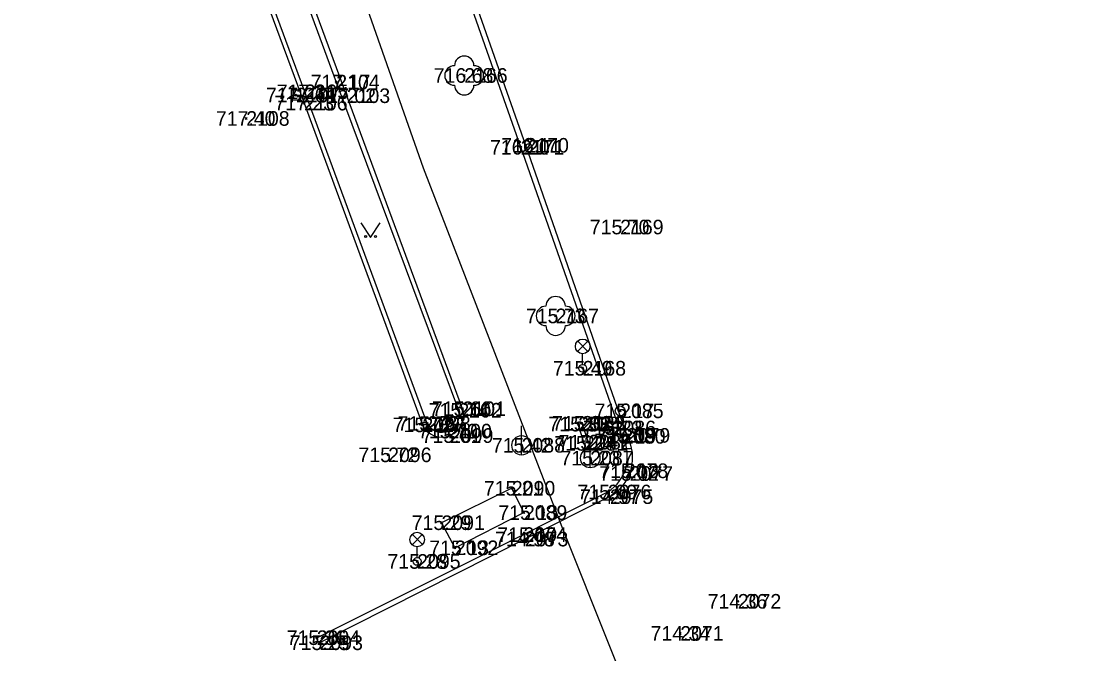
# Model space of a CAD drawing. Extents: x -844765 to -843273, y -997542 to -995529.
# Drawn here: x -844610.3 to -844555.2, y -995987.5 to -995955 of the extents above; entities that cross this region are included whole.
import ezdxf

# ---------------------------------------------------------------- set-up
doc = ezdxf.new("R2010")
doc.units = 0
for name, color, linetype in [('Betonový strop', 7, 'Continuous'), ('Bod', 7, 'Continuous'), ('Dno', 7, 'Continuous'), ('Doplněk polohopisu', 7, 'Continuous'), ('Groma', 7, 'Continuous'), ('Klenba', 7, 'Continuous'), ('Osa', 7, 'Continuous'), ('Sítě podzemní nerozlišené', 7, 'Continuous'), ('Výškopis', 7, 'Continuous'), ('Číslo bodu', 7, 'Continuous'), ('Řezy', 7, 'Continuous')]:
    doc.layers.add(name, color=color, linetype=linetype)

msp = doc.modelspace()

# ---------------------------------------------------------------- linework, layer by layer
at = {"layer": 'Betonový strop'}
for points in [[(-844629.12, -995861.21), (-844625.65, -995859.15), (-844621.49, -995856.6), (-844620.48, -995855.21), (-844619.24, -995854.94), (-844616.52, -995865.52), (-844610.55, -995885.46), (-844605.08, -995902.6), (-844600.8, -995914.77), (-844593.72, -995934.94), (-844584.42, -995961.39), (-844579.21, -995976.3)], [(-844579.45, -995976.35), (-844584.66, -995961.49), (-844593.98, -995934.98), (-844601.34, -995914.07), (-844605.29, -995902.68), (-844610.78, -995885.51), (-844616.77, -995865.64), (-844619.45, -995855.22), (-844620.38, -995855.56), (-844621.35, -995856.86), (-844628.99, -995861.43)], [(-844606.82, -995923.77), (-844594.15, -995958.14), (-844587.87, -995975.01)], [(-844587.66, -995974.93), (-844593.61, -995958.84), (-844606.58, -995923.7)], [(-844608.68, -995924.48), (-844595.8, -995959.22), (-844589.72, -995975.76)], [(-844589.47, -995975.69), (-844595.77, -995958.64), (-844608.43, -995924.4)], [(-844595.15, -995986.7), (-844584.52, -995981.4), (-844580.18, -995979.21)], [(-844580.08, -995979.45), (-844584.45, -995981.63), (-844595.01, -995986.96)]]:
    msp.add_lwpolyline(points, dxfattribs=at)
for centre, radius, start, end in [((-844588.717, -995975.278), 1.113, 205.6529, 18.2373), ((-844588.705, -995975.269), 0.874, 208.8225, 17.2285), ((-844581.342, -995977.39), 2.159, 302.5632, 28.7994), ((-844581.221, -995977.44), 2.312, 299.5827, 29.538)]:
    msp.add_arc(centre, radius, start, end, dxfattribs=at)
at = {"layer": 'Bod'}
msp.add_circle((-844579.55, -995975.04), 0.25, dxfattribs=at)
at = {"layer": 'Dno'}
msp.add_lwpolyline([(-844592.888, -995965.38), (-844592.388, -995966.13), (-844591.888, -995965.38)], dxfattribs=at)
for centre in [(-844592.638, -995966.08), (-844592.138, -995966.08)]:
    msp.add_circle(centre, 0.05, dxfattribs=at)
at = {"layer": 'Doplněk polohopisu'}
for p, q in [((-844596.47, -995958.81), (-844595.97, -995958.81)), ((-844584.62, -995977.31), (-844584.62, -995975.81)), ((-844580.19, -995975.92), (-844579.69, -995975.92)), ((-844581.09, -995977.97), (-844581.09, -995976.47))]:
    msp.add_line(p, q, dxfattribs=at)
for points in [[(-844596.47, -995959.06), (-844595.97, -995959.06), (-844595.97, -995958.56), (-844596.47, -995958.56)], [(-844580.19, -995976.17), (-844579.69, -995976.17), (-844579.69, -995975.67), (-844580.19, -995975.67)]]:
    msp.add_lwpolyline(points, close=True, dxfattribs=at)
for centre in [(-844584.62, -995976.81), (-844581.09, -995977.47)]:
    msp.add_circle(centre, 0.5, dxfattribs=at)
at = {"layer": 'Groma'}
for p, q in [((-844581.744, -995971.988), (-844581.216, -995971.46)), ((-844581.208, -995971.985), (-844581.736, -995971.456)), ((-844581.48, -995972.65), (-844581.48, -995972.1)), ((-844590.254, -995981.918), (-844589.726, -995981.39)), ((-844589.718, -995981.915), (-844590.246, -995981.386)), ((-844589.99, -995982.58), (-844589.99, -995982.03))]:
    msp.add_line(p, q, dxfattribs=at)
for centre, radius in [((-844581.48, -995971.725), 0.375), ((-844581.48, -995972.85), 0.2), ((-844589.99, -995981.655), 0.375), ((-844589.99, -995982.78), 0.2)]:
    msp.add_circle(centre, radius, dxfattribs=at)
at = {"layer": 'Klenba'}
for p, q in [((-844581.71, -995975.72), (-844581.52, -995975.68)), ((-844581.41, -995976.71), (-844581.71, -995975.72)), ((-844581.52, -995975.68), (-844581.19, -995976.65)), ((-844581.19, -995976.65), (-844581.41, -995976.71)), ((-844585.12, -995979.02), (-844588.74, -995980.79)), ((-844584.5, -995980.27), (-844585.12, -995979.02)), ((-844588.05, -995982.08), (-844584.5, -995980.27)), ((-844588.74, -995980.79), (-844588.05, -995982.08))]:
    msp.add_line(p, q, dxfattribs=at)
at = {"layer": 'Osa'}
msp.add_lwpolyline([(-844555.208, -996045.307), (-844559.6, -996036.37), (-844563.495, -996027.16), (-844571.238, -996008.81), (-844575.085, -995999.67), (-844582.535, -995981.015), (-844589.66, -995962.57), (-844596.305, -995943.685), (-844602.165, -995924.63), (-844608.085, -995905.52), (-844613.78, -995886.51), (-844619.57, -995867.42), (-844624.395, -995848.01), (-844628.94, -995828.61), (-844632.81, -995809.025), (-844636.18, -995789.375)], dxfattribs=at)
at = {"layer": 'Sítě podzemní nerozlišené'}
for p, q in [((-844587.57, -995957.8), (-844587.62, -995957.75)), ((-844587.57, -995957.8), (-844587.62, -995957.85)), ((-844587.57, -995957.8), (-844587.52, -995957.75)), ((-844587.57, -995957.8), (-844587.52, -995957.85)), ((-844594.15, -995958.14), (-844594.2, -995958.09)), ((-844594.15, -995958.14), (-844594.2, -995958.19)), ((-844594.15, -995958.14), (-844594.1, -995958.09)), ((-844594.15, -995958.14), (-844594.1, -995958.19)), ((-844596.22, -995958.81), (-844596.27, -995958.76)), ((-844596.22, -995958.81), (-844596.27, -995958.86)), ((-844596.22, -995958.81), (-844596.17, -995958.76)), ((-844596.22, -995958.81), (-844596.17, -995958.86)), ((-844595.77, -995958.64), (-844595.82, -995958.59)), ((-844595.77, -995958.64), (-844595.82, -995958.69)), ((-844595.77, -995958.64), (-844595.72, -995958.59)), ((-844595.77, -995958.64), (-844595.72, -995958.69)), ((-844593.61, -995958.84), (-844593.66, -995958.79)), ((-844593.61, -995958.84), (-844593.66, -995958.89)), ((-844593.61, -995958.84), (-844593.56, -995958.79)), ((-844593.61, -995958.84), (-844593.56, -995958.89)), ((-844595.8, -995959.22), (-844595.85, -995959.17)), ((-844595.8, -995959.22), (-844595.85, -995959.27)), ((-844595.8, -995959.22), (-844595.75, -995959.17)), ((-844595.8, -995959.22), (-844595.75, -995959.27)), ((-844598.78, -995960.01), (-844598.83, -995959.96)), ((-844598.78, -995960.01), (-844598.83, -995960.06)), ((-844598.78, -995960.01), (-844598.73, -995959.96)), ((-844598.78, -995960.01), (-844598.73, -995960.06)), ((-844584.66, -995961.49), (-844584.71, -995961.44)), ((-844584.66, -995961.49), (-844584.71, -995961.54)), ((-844584.66, -995961.49), (-844584.61, -995961.44)), ((-844584.66, -995961.49), (-844584.61, -995961.54)), ((-844584.42, -995961.39), (-844584.47, -995961.34)), ((-844584.42, -995961.39), (-844584.47, -995961.44)), ((-844584.42, -995961.39), (-844584.37, -995961.34)), ((-844584.42, -995961.39), (-844584.37, -995961.44)), ((-844579.55, -995965.59), (-844579.6, -995965.54)), ((-844579.55, -995965.59), (-844579.6, -995965.64)), ((-844579.55, -995965.59), (-844579.5, -995965.54)), ((-844579.55, -995965.59), (-844579.5, -995965.64)), ((-844582.87, -995970.16), (-844582.92, -995970.11)), ((-844582.87, -995970.16), (-844582.82, -995970.11)), ((-844582.87, -995970.16), (-844582.92, -995970.21)), ((-844582.87, -995970.16), (-844582.82, -995970.21)), ((-844581.48, -995972.85), (-844581.53, -995972.8)), ((-844581.48, -995972.85), (-844581.53, -995972.9)), ((-844581.48, -995972.85), (-844581.43, -995972.8)), ((-844581.48, -995972.85), (-844581.43, -995972.9)), ((-844587.87, -995975.01), (-844587.92, -995974.96)), ((-844587.87, -995975.01), (-844587.92, -995975.06)), ((-844587.87, -995975.01), (-844587.82, -995974.96)), ((-844587.87, -995975.01), (-844587.82, -995975.06)), ((-844587.66, -995974.93), (-844587.71, -995974.88)), ((-844587.66, -995974.93), (-844587.71, -995974.98)), ((-844587.66, -995974.93), (-844587.61, -995974.88)), ((-844587.66, -995974.93), (-844587.61, -995974.98)), ((-844579.55, -995975.04), (-844579.6, -995974.99)), ((-844579.55, -995975.04), (-844579.6, -995975.09)), ((-844579.55, -995975.04), (-844579.5, -995974.99)), ((-844579.55, -995975.04), (-844579.5, -995975.09)), ((-844581.52, -995975.68), (-844581.57, -995975.63)), ((-844581.52, -995975.68), (-844581.47, -995975.63)), ((-844589.72, -995975.76), (-844589.77, -995975.71)), ((-844589.72, -995975.76), (-844589.77, -995975.81)), ((-844589.72, -995975.76), (-844589.67, -995975.71)), ((-844589.72, -995975.76), (-844589.67, -995975.81)), ((-844589.47, -995975.69), (-844589.52, -995975.64)), ((-844589.47, -995975.69), (-844589.52, -995975.74)), ((-844589.47, -995975.69), (-844589.42, -995975.64)), ((-844589.47, -995975.69), (-844589.42, -995975.74)), ((-844588.38, -995976.08), (-844588.43, -995976.03)), ((-844588.38, -995976.08), (-844588.43, -995976.13)), ((-844588.38, -995976.08), (-844588.33, -995976.03)), ((-844588.38, -995976.08), (-844588.33, -995976.13)), ((-844581.71, -995975.72), (-844581.76, -995975.67)), ((-844581.71, -995975.72), (-844581.76, -995975.77)), ((-844581.71, -995975.72), (-844581.66, -995975.67)), ((-844581.71, -995975.72), (-844581.66, -995975.77)), ((-844581.52, -995975.68), (-844581.57, -995975.73)), ((-844581.52, -995975.68), (-844581.47, -995975.73)), ((-844579.94, -995975.92), (-844579.99, -995975.87)), ((-844579.94, -995975.92), (-844579.99, -995975.97)), ((-844579.94, -995975.92), (-844579.89, -995975.87)), ((-844579.94, -995975.92), (-844579.89, -995975.97)), ((-844588.3, -995976.31), (-844588.35, -995976.26)), ((-844588.3, -995976.31), (-844588.35, -995976.36)), ((-844588.3, -995976.31), (-844588.25, -995976.26)), ((-844588.3, -995976.31), (-844588.25, -995976.36)), ((-844581.41, -995976.71), (-844581.46, -995976.66)), ((-844581.41, -995976.71), (-844581.46, -995976.76)), ((-844581.41, -995976.71), (-844581.36, -995976.66)), ((-844581.41, -995976.71), (-844581.36, -995976.76)), ((-844581.19, -995976.65), (-844581.24, -995976.6)), ((-844581.19, -995976.65), (-844581.24, -995976.7)), ((-844581.19, -995976.65), (-844581.14, -995976.6)), ((-844581.19, -995976.65), (-844581.14, -995976.7)), ((-844579.45, -995976.35), (-844579.5, -995976.3)), ((-844579.45, -995976.35), (-844579.5, -995976.4)), ((-844579.45, -995976.35), (-844579.4, -995976.3)), ((-844579.45, -995976.35), (-844579.4, -995976.4)), ((-844579.21, -995976.3), (-844579.26, -995976.25)), ((-844579.21, -995976.3), (-844579.26, -995976.35)), ((-844579.21, -995976.3), (-844579.16, -995976.25)), ((-844579.21, -995976.3), (-844579.16, -995976.35)), ((-844591.48, -995977.3), (-844591.53, -995977.25)), ((-844591.48, -995977.3), (-844591.43, -995977.25)), ((-844584.62, -995976.81), (-844584.67, -995976.76)), ((-844584.62, -995976.81), (-844584.67, -995976.86)), ((-844584.62, -995976.81), (-844584.57, -995976.76)), ((-844584.62, -995976.81), (-844584.57, -995976.86)), ((-844591.48, -995977.3), (-844591.53, -995977.35)), ((-844591.48, -995977.3), (-844591.43, -995977.35)), ((-844581.09, -995977.47), (-844581.14, -995977.42)), ((-844581.09, -995977.47), (-844581.14, -995977.52)), ((-844581.09, -995977.47), (-844581.04, -995977.42)), ((-844581.09, -995977.47), (-844581.04, -995977.52)), ((-844579.31, -995978.12), (-844579.36, -995978.07)), ((-844579.31, -995978.12), (-844579.36, -995978.17)), ((-844579.31, -995978.12), (-844579.26, -995978.07)), ((-844579.31, -995978.12), (-844579.26, -995978.17)), ((-844579.06, -995978.26), (-844579.11, -995978.21)), ((-844579.06, -995978.26), (-844579.11, -995978.31)), ((-844579.06, -995978.26), (-844579.01, -995978.21)), ((-844579.06, -995978.26), (-844579.01, -995978.31)), ((-844585.12, -995979.02), (-844585.17, -995978.97)), ((-844585.12, -995979.02), (-844585.17, -995979.07)), ((-844585.12, -995979.02), (-844585.07, -995978.97)), ((-844585.12, -995979.02), (-844585.07, -995979.07)), ((-844580.18, -995979.21), (-844580.23, -995979.16)), ((-844580.18, -995979.21), (-844580.23, -995979.26)), ((-844580.18, -995979.21), (-844580.13, -995979.16)), ((-844580.18, -995979.21), (-844580.13, -995979.26)), ((-844580.08, -995979.45), (-844580.13, -995979.4)), ((-844580.08, -995979.45), (-844580.13, -995979.5)), ((-844580.08, -995979.45), (-844580.03, -995979.4)), ((-844580.08, -995979.45), (-844580.03, -995979.5)), ((-844584.5, -995980.27), (-844584.55, -995980.22)), ((-844584.5, -995980.27), (-844584.55, -995980.32)), ((-844584.5, -995980.27), (-844584.45, -995980.22)), ((-844584.5, -995980.27), (-844584.45, -995980.32)), ((-844588.74, -995980.79), (-844588.79, -995980.74)), ((-844588.74, -995980.79), (-844588.79, -995980.84)), ((-844588.74, -995980.79), (-844588.69, -995980.74)), ((-844588.74, -995980.79), (-844588.69, -995980.84)), ((-844584.52, -995981.4), (-844584.57, -995981.35)), ((-844584.52, -995981.4), (-844584.57, -995981.45)), ((-844584.52, -995981.4), (-844584.47, -995981.35)), ((-844584.52, -995981.4), (-844584.47, -995981.45)), ((-844584.45, -995981.63), (-844584.5, -995981.58)), ((-844584.45, -995981.63), (-844584.5, -995981.68)), ((-844584.45, -995981.63), (-844584.4, -995981.58)), ((-844584.45, -995981.63), (-844584.4, -995981.68)), ((-844588.05, -995982.08), (-844588.1, -995982.03)), ((-844588.05, -995982.08), (-844588.1, -995982.13)), ((-844588.05, -995982.08), (-844588, -995982.03)), ((-844588.05, -995982.08), (-844588, -995982.13)), ((-844589.99, -995982.78), (-844590.04, -995982.73)), ((-844589.99, -995982.78), (-844590.04, -995982.83)), ((-844589.99, -995982.78), (-844589.94, -995982.73)), ((-844589.99, -995982.78), (-844589.94, -995982.83)), ((-844573.5, -995984.83), (-844573.55, -995984.78)), ((-844573.5, -995984.83), (-844573.55, -995984.88)), ((-844573.5, -995984.83), (-844573.45, -995984.78)), ((-844573.5, -995984.83), (-844573.45, -995984.88)), ((-844595.15, -995986.7), (-844595.2, -995986.65)), ((-844595.15, -995986.7), (-844595.1, -995986.65)), ((-844576.46, -995986.48), (-844576.51, -995986.43)), ((-844576.46, -995986.48), (-844576.51, -995986.53)), ((-844576.46, -995986.48), (-844576.41, -995986.43)), ((-844576.46, -995986.48), (-844576.41, -995986.53)), ((-844595.15, -995986.7), (-844595.2, -995986.75)), ((-844595.15, -995986.7), (-844595.1, -995986.75)), ((-844595.01, -995986.96), (-844595.06, -995986.91)), ((-844595.01, -995986.96), (-844595.06, -995987.01)), ((-844595.01, -995986.96), (-844594.96, -995986.91)), ((-844595.01, -995986.96), (-844594.96, -995987.01))]:
    msp.add_line(p, q, dxfattribs=at)
at = {"layer": 'Výškopis'}
for centre in [(-844587.57, -995957.8), (-844582.87, -995970.16)]:
    msp.add_circle(centre, 0.0005, dxfattribs=at)
for centre, start, end in [((-844587.57, -995957.3), 0, 180), ((-844588.07, -995957.8), 90, 270), ((-844587.07, -995957.8), 270, 90), ((-844587.57, -995958.3), 180, 360), ((-844582.87, -995969.66), 0, 180), ((-844583.37, -995970.16), 90, 270), ((-844582.37, -995970.16), 270, 90), ((-844582.87, -995970.66), 180, 360)]:
    msp.add_arc(centre, 0.5, start, end, dxfattribs=at)

# ---------------------------------------------------------------- texts
at = {"layer": 'Číslo bodu'}
for s, p in [('2166', (-844587.57, -995958.175)), ('2104', (-844594.15, -995958.515)), ('2107', (-844596.22, -995959.185)), ('2105', (-844595.77, -995959.015)), ('2103', (-844593.61, -995959.215)), ('2106', (-844595.8, -995959.595)), ('2108', (-844598.78, -995960.385)), ('2171', (-844584.66, -995961.865)), ('2170', (-844584.42, -995961.765)), ('2169', (-844579.55, -995965.965)), ('2167', (-844582.87, -995970.535)), ('2168', (-844581.48, -995973.225)), ('2102', (-844587.87, -995975.385)), ('2101', (-844587.66, -995975.305)), ('2085', (-844579.55, -995975.415)), ('2097', (-844589.72, -995976.135)), ('2098', (-844589.47, -995976.065)), ('2084', (-844581.71, -995976.095)), ('2083', (-844581.52, -995976.055)), ('2086', (-844579.94, -995976.295)), ('2100', (-844588.38, -995976.455)), ('2099', (-844588.3, -995976.685)), ('2080', (-844579.45, -995976.725)), ('2079', (-844579.21, -995976.675)), ('2088', (-844584.62, -995977.185)), ('2081', (-844581.41, -995977.085)), ('2082', (-844581.19, -995977.025)), ('2096', (-844591.48, -995977.675)), ('2087', (-844581.09, -995977.845)), ('2078', (-844579.31, -995978.495)), ('2077', (-844579.06, -995978.635)), ('2090', (-844585.12, -995979.395)), ('2076', (-844580.18, -995979.585)), ('2075', (-844580.08, -995979.825)), ('2089', (-844584.5, -995980.645)), ('2091', (-844588.74, -995981.165)), ('2074', (-844584.52, -995981.775)), ('2092', (-844588.05, -995982.455)), ('2073', (-844584.45, -995982.005)), ('2095', (-844589.99, -995983.155)), ('2072', (-844573.5, -995985.205)), ('2071', (-844576.46, -995986.855)), ('2094', (-844595.15, -995987.075)), ('2093', (-844595.01, -995987.335))]:
    msp.add_text(s, height=0.75, dxfattribs=at).set_placement(p)
at = {"layer": 'Řezy'}
for s, p in [('716.68', (-844589.141, -995958.175)), ('717.17', (-844595.467, -995958.515)), ('717.26', (-844597.77, -995959.185)), ('717.31', (-844597.211, -995959.015)), ('717.02', (-844595.172, -995959.215)), ('717.23', (-844597.329, -995959.595)), ('717.40', (-844600.342, -995960.385)), ('716.20', (-844586.243, -995961.865)), ('716.11', (-844585.669, -995961.765)), ('715.70', (-844581.112, -995965.965)), ('715.73', (-844584.399, -995970.535)), ('715.49', (-844583.012, -995973.225)), ('715.74', (-844589.399, -995975.385)), ('715.66', (-844589.231, -995975.305)), ('715.17', (-844580.867, -995975.415)), ('715.72', (-844591.249, -995976.135)), ('715.78', (-844590.999, -995976.065)), ('715.33', (-844583.239, -995976.095)), ('715.32', (-844583.049, -995976.055)), ('715.23', (-844581.469, -995976.295)), ('715.70', (-844589.942, -995976.455)), ('715.61', (-844589.762, -995976.685)), ('715.09', (-844580.775, -995976.675)), ('715.19', (-844580.77, -995976.725)), ('715.42', (-844586.149, -995977.185)), ('715.24', (-844582.939, -995977.085)), ('715.24', (-844582.719, -995977.025)), ('715.72', (-844593.009, -995977.675)), ('715.23', (-844582.619, -995977.845)), ('715.13', (-844580.627, -995978.495)), ('715.02', (-844580.622, -995978.635)), ('715.21', (-844586.561, -995979.395)), ('715.09', (-844581.745, -995979.585)), ('714.97', (-844581.612, -995979.825)), ('715.13', (-844585.817, -995980.645)), ('715.29', (-844590.272, -995981.165)), ('715.10', (-844585.869, -995981.775)), ('715.13', (-844589.367, -995982.455)), ('714.98', (-844585.982, -995982.005)), ('715.28', (-844591.519, -995983.155)), ('714.36', (-844575.05, -995985.205)), ('714.34', (-844577.989, -995986.855)), ('715.36', (-844596.7, -995987.075)), ('715.25', (-844596.539, -995987.335))]:
    msp.add_text(s, height=0.75, dxfattribs=at).set_placement(p)

doc.saveas('drawing.dxf')
